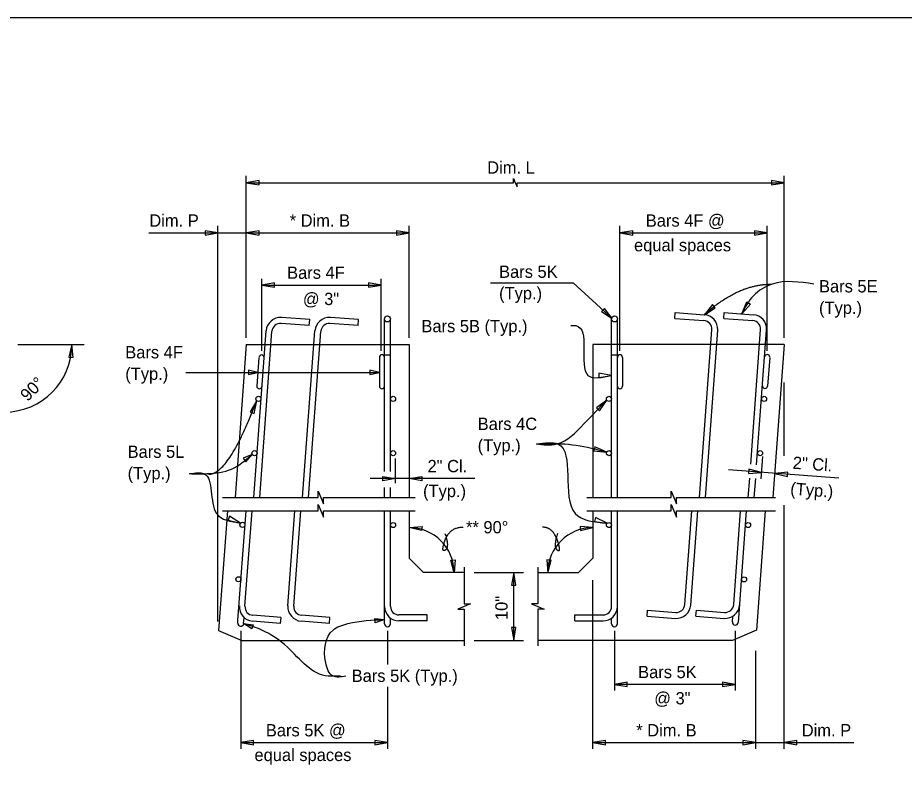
# Model space of a CAD drawing. Extents: x 120784.3 to 120844.8, y 120560 to 120604.3.
# Drawn here: x 120800.18 to 120811.07, y 120593.34 to 120602.85 of the extents above; entities that cross this region are included whole.
import ezdxf

# ---------------------------------------------------------------- set-up
doc = ezdxf.new("R2010")
doc.units = 0
for name, color, linetype in [('ActivePts-ConstElements', 7, 'Continuous'), ('AdhocPoint_dp', 7, 'Continuous'), ('PlotBorder_dp', 7, 'Continuous'), ('Rebar', 7, 'Continuous'), ('SheetBorder_dp', 7, 'Continuous')]:
    doc.layers.add(name, color=color, linetype=linetype)

# ---------------------------------------------------------------- blocks, each defined once
blk = doc.blocks.new('Terminator-Arrow')
at = {"layer": 'PlotBorder_dp'}
blk.add_lwpolyline([(0, 0), (-0.00041, 0.000069), (-0.00041, -0.000069)], close=True, dxfattribs=at)

msp = doc.modelspace()

# ---------------------------------------------------------------- linework, layer by layer
at = {"layer": 'ActivePts-ConstElements'}
msp.add_lwpolyline([(120790.703, 120583.387), (120821.491, 120583.387), (120821.491, 120602.846), (120790.703, 120602.846)], close=True, dxfattribs=at)
at = {"layer": 'AdhocPoint_dp'}
for p, q in [((120802.986, 120598.834), (120802.847, 120596.955)), ((120802.986, 120598.834), (120804.986, 120598.834)), ((120804.986, 120598.833), (120804.986, 120596.955)), ((120809.594, 120598.834), (120807.243, 120598.834)), ((120807.243, 120598.833), (120807.243, 120596.955)), ((120809.594, 120598.834), (120809.455, 120596.955)), ((120802.753, 120596.794), (120802.644, 120595.325)), ((120804.986, 120596.794), (120804.986, 120596.212)), ((120807.243, 120596.794), (120807.243, 120596.212)), ((120809.361, 120596.794), (120809.252, 120595.326)), ((120805.163, 120596.035), (120804.986, 120596.212)), ((120807.066, 120596.035), (120807.243, 120596.212)), ((120805.663, 120596.035), (120805.163, 120596.035)), ((120806.566, 120596.035), (120807.066, 120596.035)), ((120802.644, 120595.325), (120802.931, 120595.201)), ((120809.252, 120595.326), (120808.96, 120595.201)), ((120802.931, 120595.202), (120805.663, 120595.202)), ((120808.96, 120595.202), (120806.566, 120595.202))]:
    msp.add_line(p, q, dxfattribs=at)
at = {"layer": 'PlotBorder_dp'}
for p, q in [((120802.986, 120598.916), (120802.986, 120600.906)), ((120802.986, 120598.916), (120802.986, 120600.906)), ((120809.594, 120598.916), (120809.594, 120600.906)), ((120809.594, 120598.916), (120809.594, 120600.906)), ((120802.635, 120595.433), (120802.635, 120600.29)), ((120802.635, 120595.433), (120802.635, 120600.29)), ((120804.986, 120598.916), (120804.986, 120600.29)), ((120804.986, 120598.916), (120804.986, 120600.29)), ((120807.576, 120598.755), (120807.576, 120600.29)), ((120807.576, 120598.755), (120807.576, 120600.29)), ((120809.386, 120598.755), (120809.386, 120600.29)), ((120809.386, 120598.755), (120809.386, 120600.29)), ((120801.79, 120600.206), (120804.986, 120600.206)), ((120801.79, 120600.206), (120804.986, 120600.206)), ((120807.576, 120600.206), (120809.386, 120600.206)), ((120807.576, 120600.206), (120809.386, 120600.206)), ((120803.175, 120598.755), (120803.175, 120599.641)), ((120803.175, 120598.755), (120803.175, 120599.641)), ((120804.644, 120598.755), (120804.644, 120599.641)), ((120804.644, 120598.755), (120804.644, 120599.641)), ((120805.985, 120599.592), (120807, 120599.592)), ((120805.985, 120599.592), (120807, 120599.592)), ((120803.175, 120599.565), (120804.644, 120599.565)), ((120803.175, 120599.565), (120804.644, 120599.565)), ((120807.509, 120599.184), (120807.509, 120599.184)), ((120807.509, 120599.184), (120807.509, 120599.184)), ((120800.18, 120598.834), (120800.994, 120598.834)), ((120800.18, 120598.834), (120800.994, 120598.834)), ((120802.242, 120598.491), (120804.621, 120598.491)), ((120802.242, 120598.491), (120804.621, 120598.491)), ((120809.594, 120597.468), (120809.594, 120598.37)), ((120809.594, 120597.468), (120809.594, 120598.37)), ((120804.819, 120597.134), (120804.819, 120597.435)), ((120804.819, 120597.134), (120804.819, 120597.435)), ((120809.328, 120597.459), (120809.308, 120597.186)), ((120809.328, 120597.459), (120809.308, 120597.186)), ((120810.265, 120597.193), (120808.908, 120597.294)), ((120810.265, 120597.193), (120808.908, 120597.294)), ((120805.794, 120597.188), (120804.509, 120597.188)), ((120805.794, 120597.188), (120804.509, 120597.188)), ((120809.594, 120593.872), (120809.594, 120596.861)), ((120809.594, 120593.872), (120809.594, 120596.861)), ((120805.784, 120596.035), (120806.392, 120596.035)), ((120805.784, 120596.035), (120806.392, 120596.035)), ((120806.272, 120595.201), (120806.272, 120596.035)), ((120806.272, 120595.201), (120806.272, 120596.035)), ((120807.243, 120593.872), (120807.243, 120595.943)), ((120807.243, 120593.872), (120807.243, 120595.943)), ((120802.917, 120595.319), (120802.917, 120593.872)), ((120802.917, 120595.319), (120802.917, 120593.872)), ((120804.72, 120595.319), (120804.72, 120594.904)), ((120804.72, 120595.319), (120804.72, 120594.904)), ((120807.509, 120595.319), (120807.509, 120594.587)), ((120807.509, 120595.319), (120807.509, 120594.587)), ((120808.99, 120595.319), (120808.99, 120594.587)), ((120808.99, 120595.319), (120808.99, 120594.587)), ((120805.784, 120595.201), (120806.392, 120595.201)), ((120805.784, 120595.201), (120806.392, 120595.201)), ((120809.243, 120593.872), (120809.243, 120595.074)), ((120809.243, 120593.872), (120809.243, 120595.074)), ((120804.72, 120594.632), (120804.72, 120593.872)), ((120804.72, 120594.632), (120804.72, 120593.872)), ((120807.509, 120594.663), (120808.99, 120594.663)), ((120807.509, 120594.663), (120808.99, 120594.663)), ((120802.917, 120593.947), (120804.72, 120593.947)), ((120802.917, 120593.947), (120804.72, 120593.947)), ((120807.243, 120593.947), (120810.449, 120593.947)), ((120807.243, 120593.947), (120810.449, 120593.947))]:
    msp.add_line(p, q, dxfattribs=at)
for points in [[(120802.986, 120600.821), (120806.267, 120600.821), (120806.267, 120600.872), (120806.29, 120600.821), (120806.312, 120600.769), (120806.312, 120600.821), (120809.594, 120600.821)], [(120802.986, 120600.821), (120806.267, 120600.821), (120806.267, 120600.872), (120806.29, 120600.821), (120806.312, 120600.769), (120806.312, 120600.821), (120809.594, 120600.821)], [(120807, 120599.592), (120807.482, 120599.152)], [(120807, 120599.592), (120807.482, 120599.152)], [(120802.693, 120596.955), (120803.868, 120596.955), (120803.868, 120597.033), (120803.902, 120596.955), (120803.935, 120596.878), (120803.935, 120596.955), (120805.061, 120596.955)], [(120802.693, 120596.955), (120803.868, 120596.955), (120803.868, 120597.033), (120803.902, 120596.955), (120803.935, 120596.878), (120803.935, 120596.955), (120805.061, 120596.955)], [(120807.167, 120596.955), (120808.203, 120596.955), (120808.203, 120597.033), (120808.236, 120596.955), (120808.27, 120596.878), (120808.27, 120596.955), (120809.488, 120596.955)], [(120807.167, 120596.955), (120808.203, 120596.955), (120808.203, 120597.033), (120808.236, 120596.955), (120808.27, 120596.878), (120808.27, 120596.955), (120809.488, 120596.955)], [(120802.693, 120596.794), (120803.868, 120596.794), (120803.868, 120596.871), (120803.902, 120596.794), (120803.935, 120596.716), (120803.935, 120596.794), (120805.061, 120596.794)], [(120802.693, 120596.794), (120803.868, 120596.794), (120803.868, 120596.871), (120803.902, 120596.794), (120803.935, 120596.716), (120803.935, 120596.794), (120805.061, 120596.794)], [(120807.167, 120596.794), (120808.203, 120596.794), (120808.203, 120596.871), (120808.236, 120596.794), (120808.27, 120596.716), (120808.27, 120596.794), (120809.488, 120596.794)], [(120807.167, 120596.794), (120808.203, 120596.794), (120808.203, 120596.871), (120808.236, 120596.794), (120808.27, 120596.716), (120808.27, 120596.794), (120809.488, 120596.794)], [(120805.663, 120596.102), (120805.663, 120595.652), (120805.741, 120595.652), (120805.586, 120595.584), (120805.663, 120595.584), (120805.663, 120595.134)], [(120805.663, 120596.102), (120805.663, 120595.652), (120805.741, 120595.652), (120805.586, 120595.584), (120805.663, 120595.584), (120805.663, 120595.134)], [(120806.566, 120596.102), (120806.566, 120595.652), (120806.488, 120595.652), (120806.643, 120595.584), (120806.566, 120595.584), (120806.566, 120595.134)], [(120806.566, 120596.102), (120806.566, 120595.652), (120806.488, 120595.652), (120806.643, 120595.584), (120806.566, 120595.584), (120806.566, 120595.134)]]:
    msp.add_lwpolyline(points, dxfattribs=at)
for points in [[(120809.072, 120599.211), (120809.134, 120599.357), (120809.179, 120599.328)], [(120809.072, 120599.211), (120809.134, 120599.357), (120809.179, 120599.328)], [(120807.482, 120599.152), (120807.385, 120599.277), (120807.349, 120599.238)], [(120807.482, 120599.152), (120807.385, 120599.277), (120807.349, 120599.238)], [(120808.613, 120599.2), (120808.746, 120599.286), (120808.711, 120599.325)], [(120808.613, 120599.2), (120808.746, 120599.286), (120808.711, 120599.325)], [(120800.843, 120598.834), (120800.805, 120598.68), (120800.857, 120598.676)], [(120800.843, 120598.834), (120800.805, 120598.68), (120800.857, 120598.676)], [(120803.128, 120598.491), (120803.011, 120598.518), (120803.011, 120598.465)], [(120803.128, 120598.491), (120803.011, 120598.518), (120803.011, 120598.465)], [(120804.621, 120598.491), (120804.504, 120598.518), (120804.504, 120598.465)], [(120804.621, 120598.491), (120804.504, 120598.518), (120804.504, 120598.465)], [(120807.472, 120598.456), (120807.316, 120598.482), (120807.316, 120598.429)], [(120807.472, 120598.456), (120807.316, 120598.482), (120807.316, 120598.429)], [(120803.113, 120598.145), (120803.033, 120598.008), (120803.082, 120597.989)], [(120803.113, 120598.145), (120803.033, 120598.008), (120803.082, 120597.989)], [(120807.413, 120598.153), (120807.286, 120598.058), (120807.325, 120598.021)], [(120807.413, 120598.153), (120807.286, 120598.058), (120807.325, 120598.021)], [(120807.413, 120597.514), (120807.269, 120597.58), (120807.255, 120597.529)], [(120807.413, 120597.514), (120807.269, 120597.58), (120807.255, 120597.529)], [(120803.058, 120597.486), (120802.947, 120597.439), (120802.978, 120597.396)], [(120803.058, 120597.486), (120802.947, 120597.439), (120802.978, 120597.396)], [(120809.313, 120597.264), (120809.16, 120597.302), (120809.156, 120597.249)], [(120809.313, 120597.264), (120809.16, 120597.302), (120809.156, 120597.249)], [(120809.48, 120597.251), (120809.634, 120597.214), (120809.638, 120597.266)], [(120809.48, 120597.251), (120809.634, 120597.214), (120809.638, 120597.266)], [(120802.916, 120596.642), (120802.781, 120596.725), (120802.761, 120596.676)], [(120802.916, 120596.642), (120802.781, 120596.725), (120802.761, 120596.676)], [(120807.419, 120596.64), (120807.277, 120596.711), (120807.262, 120596.661)], [(120807.419, 120596.64), (120807.277, 120596.711), (120807.262, 120596.661)], [(120804.986, 120596.588), (120805.144, 120596.601), (120805.139, 120596.549)], [(120804.986, 120596.588), (120805.144, 120596.601), (120805.139, 120596.549)], [(120807.243, 120596.588), (120807.085, 120596.601), (120807.09, 120596.549)], [(120807.243, 120596.588), (120807.085, 120596.601), (120807.09, 120596.549)], [(120805.541, 120596.033), (120805.499, 120596.186), (120805.552, 120596.191)], [(120805.541, 120596.033), (120805.499, 120596.186), (120805.552, 120596.191)], [(120806.688, 120596.033), (120806.729, 120596.186), (120806.677, 120596.191)], [(120806.688, 120596.033), (120806.729, 120596.186), (120806.677, 120596.191)], [(120806.272, 120596.035), (120806.245, 120595.879), (120806.298, 120595.879)], [(120806.272, 120596.035), (120806.245, 120595.879), (120806.298, 120595.879)], [(120804.683, 120595.457), (120804.57, 120595.418), (120804.564, 120595.471)], [(120804.683, 120595.457), (120804.57, 120595.418), (120804.564, 120595.471)], [(120802.953, 120595.408), (120803.072, 120595.394), (120803.055, 120595.344)], [(120802.953, 120595.408), (120803.072, 120595.394), (120803.055, 120595.344)], [(120806.272, 120595.202), (120806.298, 120595.358), (120806.245, 120595.358)], [(120806.272, 120595.202), (120806.298, 120595.358), (120806.245, 120595.358)]]:
    msp.add_lwpolyline(points, close=True, dxfattribs=at)
for centre, radius, start, end in [((120800.015, 120598.833), 0.828, 270.1769, 0), ((120800.015, 120598.833), 0.828, 270.1769, 0), ((120804.981, 120596.029), 0.559, 0.3991, 89.55), ((120804.981, 120596.029), 0.559, 0.3991, 89.55), ((120807.247, 120596.029), 0.559, 90.45, 179.6009), ((120807.247, 120596.029), 0.559, 90.45, 179.6009)]:
    msp.add_arc(centre, radius, start, end, dxfattribs=at)
for points in [[(120808.613, 120599.2), (120809.024, 120599.575), (120809.434, 120599.575)], [(120808.613, 120599.2), (120809.024, 120599.575), (120809.434, 120599.575)], [(120802.527, 120597.242), (120802.771, 120597.242), (120803.113, 120598.145)], [(120802.527, 120597.242), (120802.771, 120597.242), (120803.113, 120598.145)], [(120805.426, 120596.516), (120805.484, 120596.344), (120805.373, 120596.275), (120805.485, 120596.592), (120805.648, 120596.592)], [(120805.426, 120596.516), (120805.484, 120596.344), (120805.373, 120596.275), (120805.485, 120596.592), (120805.648, 120596.592)], [(120806.81, 120596.516), (120806.752, 120596.344), (120806.863, 120596.275), (120806.75, 120596.592), (120806.624, 120596.592)], [(120806.81, 120596.516), (120806.752, 120596.344), (120806.863, 120596.275), (120806.75, 120596.592), (120806.624, 120596.592)]]:
    msp.add_open_spline(points, degree=2, dxfattribs=at)
for points in [[(120809.959, 120599.576), (120809.445, 120599.576), (120809.215, 120599.433), (120809.072, 120599.211)], [(120809.959, 120599.576), (120809.445, 120599.576), (120809.215, 120599.433), (120809.072, 120599.211)], [(120806.972, 120599.067), (120807.033, 120599.067), (120807.183, 120598.456), (120807.472, 120598.456)], [(120806.972, 120599.067), (120807.033, 120599.067), (120807.183, 120598.456), (120807.472, 120598.456)], [(120806.548, 120597.613), (120806.8, 120597.613), (120807.134, 120597.859), (120807.413, 120598.153)], [(120806.548, 120597.613), (120806.8, 120597.613), (120807.134, 120597.859), (120807.413, 120598.153)], [(120806.553, 120597.613), (120806.812, 120597.613), (120807.024, 120596.761), (120807.419, 120596.64)], [(120806.553, 120597.613), (120806.812, 120597.613), (120807.024, 120596.761), (120807.419, 120596.64)], [(120806.581, 120597.613), (120806.898, 120597.613), (120807.271, 120597.552), (120807.413, 120597.514)], [(120806.581, 120597.613), (120806.898, 120597.613), (120807.271, 120597.552), (120807.413, 120597.514)], [(120802.284, 120597.249), (120802.503, 120597.249), (120802.804, 120597.304), (120803.058, 120597.486)], [(120802.284, 120597.249), (120802.503, 120597.249), (120802.804, 120597.304), (120803.058, 120597.486)], [(120802.292, 120597.249), (120802.466, 120597.249), (120802.62, 120596.761), (120802.916, 120596.642)], [(120802.292, 120597.249), (120802.466, 120597.249), (120802.62, 120596.761), (120802.916, 120596.642)], [(120804.21, 120594.764), (120804.048, 120594.764), (120803.961, 120594.928), (120804.051, 120595.328), (120804.232, 120595.408), (120804.683, 120595.457)], [(120804.21, 120594.764), (120804.048, 120594.764), (120803.961, 120594.928), (120804.051, 120595.328), (120804.232, 120595.408), (120804.683, 120595.457)], [(120804.141, 120594.764), (120804.035, 120594.764), (120803.993, 120594.764), (120803.492, 120595.117), (120803.177, 120595.328), (120802.953, 120595.408)], [(120804.141, 120594.764), (120804.035, 120594.764), (120803.993, 120594.764), (120803.492, 120595.117), (120803.177, 120595.328), (120802.953, 120595.408)]]:
    msp.add_spline(points, degree=3, dxfattribs=at)
at = {"layer": 'Rebar'}
for p, q in [((120803.765, 120599.14), (120803.418, 120599.165)), ((120803.759, 120599.067), (120803.765, 120599.14)), ((120804.365, 120599.14), (120804.018, 120599.165)), ((120804.359, 120599.067), (120804.365, 120599.14)), ((120804.684, 120597.276), (120804.684, 120599.147)), ((120804.757, 120597.276), (120804.757, 120599.147)), ((120807.472, 120596.955), (120807.472, 120599.147)), ((120807.545, 120596.955), (120807.545, 120599.147)), ((120808.25, 120599.154), (120808.255, 120599.227)), ((120808.25, 120599.154), (120808.608, 120599.128)), ((120808.255, 120599.227), (120808.613, 120599.2)), ((120808.85, 120599.154), (120808.855, 120599.227)), ((120808.85, 120599.154), (120809.208, 120599.128)), ((120808.855, 120599.227), (120809.213, 120599.2)), ((120803.759, 120599.067), (120803.412, 120599.092)), ((120804.359, 120599.067), (120804.012, 120599.092)), ((120803.077, 120596.955), (120803.228, 120599.002)), ((120803.15, 120596.955), (120803.301, 120598.996)), ((120803.677, 120596.955), (120803.828, 120599.002)), ((120803.75, 120596.955), (120803.901, 120598.996)), ((120808.552, 120596.955), (120808.704, 120599.016)), ((120808.625, 120596.955), (120808.777, 120599.011)), ((120809.182, 120597.366), (120809.304, 120599.016)), ((120809.255, 120597.357), (120809.377, 120599.011)), ((120804.684, 120598.708), (120804.757, 120598.708)), ((120807.472, 120598.708), (120807.545, 120598.708)), ((120803.141, 120598.677), (120803.115, 120598.324)), ((120804.621, 120598.677), (120804.621, 120598.323)), ((120807.608, 120598.677), (120807.608, 120598.323)), ((120809.415, 120598.677), (120809.389, 120598.324)), ((120809.152, 120596.955), (120809.17, 120597.195)), ((120809.225, 120596.955), (120809.243, 120597.19)), ((120804.684, 120596.955), (120804.684, 120597.079)), ((120804.757, 120596.955), (120804.757, 120597.079)), ((120802.883, 120595.45), (120802.982, 120596.794)), ((120802.969, 120595.621), (120803.056, 120596.794)), ((120803.496, 120595.627), (120803.582, 120596.794)), ((120803.569, 120595.621), (120803.656, 120596.794)), ((120804.684, 120595.441), (120804.684, 120596.794)), ((120804.757, 120595.618), (120804.757, 120596.794)), ((120807.472, 120595.618), (120807.472, 120596.794)), ((120807.545, 120595.405), (120807.545, 120596.794)), ((120808.373, 120595.641), (120808.458, 120596.794)), ((120808.445, 120595.636), (120808.531, 120596.794)), ((120808.973, 120595.641), (120809.058, 120596.794)), ((120809.03, 120595.423), (120809.131, 120596.794)), ((120807.909, 120595.498), (120807.914, 120595.571)), ((120807.914, 120595.571), (120808.261, 120595.545)), ((120808.509, 120595.498), (120808.514, 120595.571)), ((120808.514, 120595.571), (120808.861, 120595.545)), ((120802.881, 120595.414), (120802.883, 120595.45)), ((120802.953, 120595.408), (120802.958, 120595.478)), ((120803.407, 120595.411), (120803.06, 120595.437)), ((120803.412, 120595.484), (120803.065, 120595.51)), ((120803.407, 120595.411), (120803.412, 120595.484)), ((120804.007, 120595.411), (120803.66, 120595.437)), ((120804.012, 120595.484), (120803.665, 120595.51)), ((120804.007, 120595.411), (120804.012, 120595.484)), ((120804.684, 120595.405), (120804.684, 120595.441)), ((120804.757, 120595.405), (120804.757, 120595.475)), ((120805.209, 120595.514), (120804.861, 120595.514)), ((120805.209, 120595.441), (120804.861, 120595.441)), ((120805.209, 120595.441), (120805.209, 120595.514)), ((120807.02, 120595.514), (120807.368, 120595.514)), ((120807.02, 120595.441), (120807.02, 120595.514)), ((120807.02, 120595.441), (120807.368, 120595.441)), ((120807.472, 120595.405), (120807.472, 120595.475)), ((120807.909, 120595.498), (120808.256, 120595.472)), ((120808.509, 120595.498), (120808.856, 120595.472)), ((120808.957, 120595.428), (120808.962, 120595.498))]:
    msp.add_line(p, q, dxfattribs=at)
for centre, radius in [((120804.72, 120599.148), 0.0365), ((120807.509, 120599.148), 0.0365), ((120803.135, 120598.167), 0.0312), ((120804.788, 120598.167), 0.0312), ((120807.441, 120598.167), 0.0312), ((120809.346, 120598.167), 0.0312), ((120803.086, 120597.5), 0.0312), ((120804.788, 120597.5), 0.0312), ((120807.441, 120597.5), 0.0312), ((120809.297, 120597.5), 0.0312), ((120802.938, 120596.62), 0.0312), ((120804.788, 120596.618), 0.0312), ((120807.441, 120596.618), 0.0312), ((120809.149, 120596.618), 0.0312), ((120802.889, 120595.952), 0.0312), ((120809.1, 120595.951), 0.0312)]:
    msp.add_circle(centre, radius, dxfattribs=at)
for centre, radius, start, end in [((120803.405, 120598.989), 0.177, 85.7768, 175.7768), ((120804.005, 120598.989), 0.177, 85.7768, 175.7768), ((120808.6, 120599.024), 0.177, 355.7766, 85.7766), ((120809.2, 120599.024), 0.177, 355.7766, 85.7766), ((120803.405, 120598.989), 0.104, 85.7768, 175.7768), ((120804.005, 120598.989), 0.104, 85.7768, 175.7768), ((120808.6, 120599.024), 0.104, 355.7766, 85.7766), ((120809.2, 120599.024), 0.104, 355.7766, 85.7766), ((120803.173, 120598.675), 0.0312, 355.7768, 175.7768), ((120804.652, 120598.677), 0.0312, 0, 180), ((120807.576, 120598.677), 0.0312, 0, 180), ((120809.384, 120598.68), 0.0312, 355.7766, 175.7766), ((120803.146, 120598.322), 0.0312, 175.7768, 355.7768), ((120804.652, 120598.323), 0.0312, 180, 0), ((120807.576, 120598.323), 0.0312, 180, 0), ((120809.358, 120598.326), 0.0312, 175.7766, 355.7766), ((120803.075, 120595.612), 0.175, 175.0466, 265.0466), ((120803.073, 120595.614), 0.104, 175.7768, 265.7768), ((120803.673, 120595.614), 0.177, 175.7768, 265.7768), ((120803.673, 120595.614), 0.104, 175.7768, 265.7768), ((120804.861, 120595.618), 0.177, 180, 270), ((120804.861, 120595.618), 0.104, 180, 270), ((120807.368, 120595.618), 0.104, 270, 360), ((120807.368, 120595.618), 0.177, 270, 360), ((120808.269, 120595.649), 0.177, 265.7766, 355.7766), ((120808.269, 120595.649), 0.104, 265.7766, 355.7766), ((120808.869, 120595.649), 0.177, 265.7766, 355.7766), ((120808.869, 120595.649), 0.104, 265.7766, 355.7766), ((120802.917, 120595.411), 0.0365, 175.7768, 355.7768), ((120804.72, 120595.405), 0.0365, 180, 0), ((120807.509, 120595.405), 0.0365, 180, 0), ((120808.993, 120595.426), 0.0365, 175.7766, 355.7766)]:
    msp.add_arc(centre, radius, start, end, dxfattribs=at)

# ---------------------------------------------------------------- block references
at = {"layer": 'PlotBorder_dp', "xscale": 381, "rotation": 180}
for p, yscale in [((120802.986, 120600.82), 384.0238095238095), ((120802.986, 120600.82), 384.0238095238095), ((120802.986, 120600.205), 384.0238095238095), ((120802.986, 120600.205), 384.0238095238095), ((120807.576, 120600.205), 384.0238095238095), ((120807.576, 120600.205), 384.0238095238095), ((120803.175, 120599.565), 384.0238095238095), ((120803.175, 120599.565), 384.0238095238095), ((120804.986, 120597.188), -384.0238095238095), ((120804.986, 120597.188), -384.0238095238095), ((120807.508, 120594.662), 384.0238095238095), ((120807.508, 120594.662), 384.0238095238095), ((120802.917, 120593.947), 384.0238095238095), ((120802.917, 120593.947), 384.0238095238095), ((120807.243, 120593.947), 384.0238095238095), ((120807.243, 120593.947), 384.0238095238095), ((120809.594, 120593.947), 384.0238095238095), ((120809.594, 120593.947), 384.0238095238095)]:
    msp.add_blockref('Terminator-Arrow', p, dxfattribs=dict(at, yscale=yscale))
at = {"layer": 'PlotBorder_dp', "xscale": 381}
for p, yscale in [((120809.593, 120600.82), 384.0238095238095), ((120809.593, 120600.82), 384.0238095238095), ((120802.635, 120600.205), 384.0238095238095), ((120802.635, 120600.205), 384.0238095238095), ((120804.986, 120600.205), 384.0238095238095), ((120804.986, 120600.205), 384.0238095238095), ((120809.386, 120600.205), 384.0238095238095), ((120809.386, 120600.205), 384.0238095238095), ((120804.643, 120599.565), 384.0238095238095), ((120804.643, 120599.565), 384.0238095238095), ((120804.819, 120597.188), -384.0238095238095), ((120804.819, 120597.188), -384.0238095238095), ((120808.99, 120594.662), 384.0238095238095), ((120808.99, 120594.662), 384.0238095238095), ((120804.72, 120593.947), 384.0238095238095), ((120804.72, 120593.947), 384.0238095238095), ((120809.243, 120593.947), 384.0238095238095), ((120809.243, 120593.947), 384.0238095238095)]:
    msp.add_blockref('Terminator-Arrow', p, dxfattribs=dict(at, yscale=yscale))

# ---------------------------------------------------------------- texts
at = {"layer": 'PlotBorder_dp'}
for s, p in [('Bars 5K', (120806.091, 120599.653)), ('Bars 5E', (120810.021, 120599.474)), ('(Typ.)', (120806.091, 120599.389)), ('(Typ.)', (120810.021, 120599.21)), ('Bars 4F', (120801.499, 120598.664)), ('(Typ.)', (120801.499, 120598.4)), ('Bars 4C', (120805.828, 120597.785)), ('(Typ.)', (120805.828, 120597.521)), ('Bars 5L', (120801.528, 120597.443)), ('(Typ.)', (120801.528, 120597.179))]:
    msp.add_text(s, height=0.1512, dxfattribs=at).set_placement(p)
at = {"layer": 'SheetBorder_dp'}
for s, p in [('Dim. L', (120805.945, 120600.932)), ('Dim. P', (120801.795, 120600.281)), ('* Dim. B', (120803.519, 120600.281)), ('Bars 4F @', (120807.893, 120600.281)), ('equal spaces', (120807.749, 120599.979)), ('Bars 4F', (120803.487, 120599.641)), ('@ 3"', (120803.681, 120599.319)), ('Bars 5B (Typ.)', (120805.137, 120598.985)), ('2" Cl.', (120805.212, 120597.266)), ('(Typ.)', (120805.157, 120596.961)), ('** 90°', (120805.685, 120596.516)), ('Bars 5K', (120807.799, 120594.738)), ('Bars 5K (Typ.)', (120804.28, 120594.692)), ('@ 3"', (120807.997, 120594.416)), ('Bars 5K @', (120803.226, 120594.023)), ('* Dim. B', (120807.776, 120594.023)), ('Dim. P', (120809.809, 120594.023)), ('equal spaces', (120803.086, 120593.72))]:
    msp.add_text(s, height=0.1512, dxfattribs=at).set_placement(p)
for s, rotation, p in [(' 90°', 45, (120800.26, 120598.088)), ('2" Cl.', 355.7766, (120809.693, 120597.31)), ('(Typ.)', 355.7766, (120809.664, 120596.992)), ('10"', 90, (120806.196, 120595.451))]:
    msp.add_text(s, height=0.1512, rotation=rotation, dxfattribs=at).set_placement(p)

doc.saveas('drawing.dxf')
